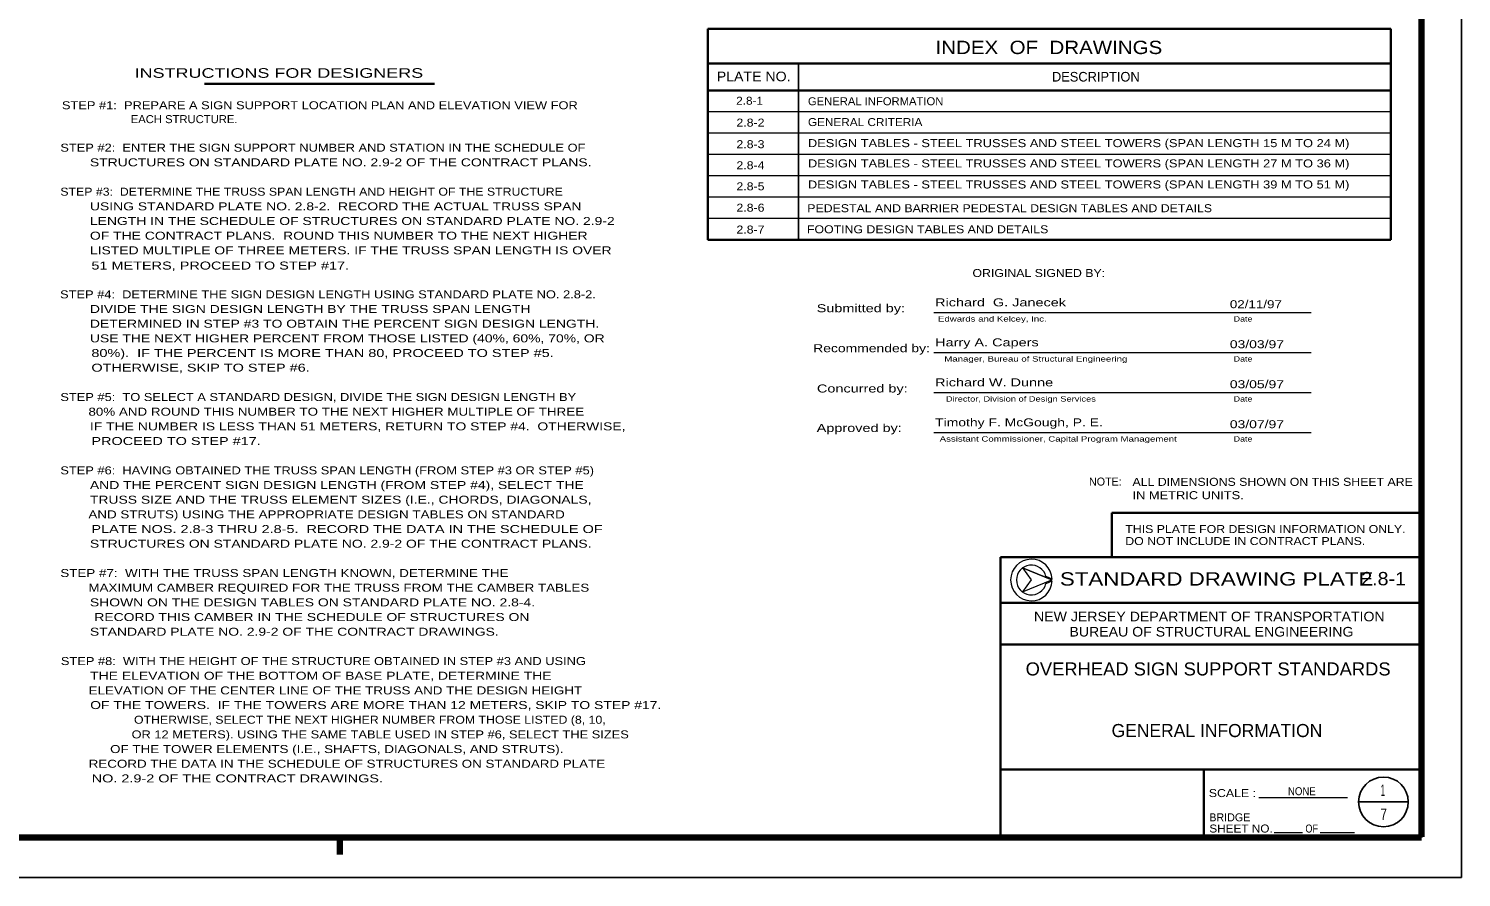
# Model space of a CAD drawing. Extents: x 312601.858 to 312602.699, y 144420.109 to 144420.704.
# Drawn here: x 312602.162 to 312602.699, y 144420.109 to 144420.428 of the extents above; entities that cross this region are included whole.
import ezdxf
from ezdxf.enums import TextEntityAlignment as Align

# ---------------------------------------------------------------- set-up
doc = ezdxf.new("R2010")
doc.units = 0
doc.header["$LTSCALE"] = 0.0012
for name, color, linetype, lineweight in [('1', 7, 'Continuous', 13), ('2', 7, 'Continuous', 25), ('39', 7, 'Continuous', 25)]:
    doc.layers.add(name, color=color, linetype=linetype, lineweight=lineweight)
doc.layers.add('4', color=7, linetype='Continuous')
doc.layers.add('51', color=7, linetype='Continuous')

msp = doc.modelspace()

# ---------------------------------------------------------------- linework, layer by layer
at = {"layer": '1', "lineweight": 35}
for p, q in [((312602.4163, 144420.3486), (312602.4163, 144420.4276)), ((312602.6724, 144420.4276), (312602.4163, 144420.4276)), ((312602.6724, 144420.3486), (312602.6724, 144420.4276)), ((312602.6724, 144420.4146), (312602.4163, 144420.4146)), ((312602.6724, 144420.4046), (312602.4163, 144420.4046)), ((312602.6724, 144420.3486), (312602.4163, 144420.3486))]:
    msp.add_line(p, q, dxfattribs=at)
at = {"layer": '1', "lineweight": 25}
msp.add_line((312602.4503, 144420.3486), (312602.4503, 144420.4146), dxfattribs=at)
at = {"layer": '1'}
for p, q in [((312602.6724, 144420.3966), (312602.4163, 144420.3966)), ((312602.6724, 144420.3886), (312602.4163, 144420.3886)), ((312602.6724, 144420.3806), (312602.4163, 144420.3806)), ((312602.6724, 144420.3726), (312602.4163, 144420.3726)), ((312602.6724, 144420.3646), (312602.4163, 144420.3646)), ((312602.6724, 144420.3566), (312602.4163, 144420.3566)), ((312602.501, 144420.3213), (312602.6425, 144420.3213)), ((312602.501, 144420.3063), (312602.6425, 144420.3063)), ((312602.501, 144420.2913), (312602.6425, 144420.2913)), ((312602.501, 144420.2763), (312602.6425, 144420.2763)), ((312602.5431, 144420.2197), (312602.5454, 144420.2207)), ((312602.6286, 144420.1263), (312602.6392, 144420.1263)), ((312602.6459, 144420.1263), (312602.6587, 144420.1263))]:
    msp.add_line(p, q, dxfattribs=at)
for points in [[(312602.5452, 144420.221), (312602.5343, 144420.2255), (312602.5452, 144420.221)], [(312602.5454, 144420.2213), (312602.5431, 144420.2223), (312602.543, 144420.2223)]]:
    msp.add_lwpolyline(points, dxfattribs=at)
for points in [[(312602.5452, 144420.221), (312602.5343, 144420.2255), (312602.5375, 144420.221), (312602.5343, 144420.2165)], [(312602.5375, 144420.221), (312602.5343, 144420.2165), (312602.5452, 144420.221), (312602.5343, 144420.2255)]]:
    msp.add_lwpolyline(points, close=True, dxfattribs=at)
for radius, start, end in [(0.0078026, 2.21392, 357.78608), (0.0056, 13.69411, 346.30589)]:
    msp.add_arc((312602.5376, 144420.221), radius, start, end, dxfattribs=at)
at = {"layer": '2', "lineweight": 35}
msp.add_line((312602.2276, 144420.407), (312602.3138, 144420.407), dxfattribs=at)
at = {"layer": '39'}
for p, q in [((312602.6988, 144420.1095), (312602.6988, 144420.7035)), ((312602.6789, 144420.1378), (312602.6603, 144420.1378)), ((312601.8578, 144420.1095), (312602.6988, 144420.1095))]:
    msp.add_line(p, q, dxfattribs=at)
at = {"layer": '39', "lineweight": 158}
for p, q in [((312602.6838, 144420.1247), (312602.6838, 144420.6645)), ((312601.9088, 144420.1245), (312602.6838, 144420.1245)), ((312602.2783, 144420.1181), (312602.2783, 144420.1245))]:
    msp.add_line(p, q, dxfattribs=at)
at = {"layer": '39', "lineweight": 35}
for p, q in [((312602.5677, 144420.2462), (312602.6838, 144420.2462)), ((312602.5677, 144420.2295), (312602.5677, 144420.2462)), ((312602.526, 144420.1245), (312602.526, 144420.2295)), ((312602.526, 144420.2124), (312602.6838, 144420.2124)), ((312602.526, 144420.1968), (312602.6838, 144420.1968)), ((312602.526, 144420.1499), (312602.6838, 144420.1499)), ((312602.6022, 144420.1248), (312602.6022, 144420.1499)), ((312602.6022, 144420.1248), (312602.6022, 144420.1499))]:
    msp.add_line(p, q, dxfattribs=at)
at = {"layer": '39', "lineweight": 13}
for p, q in [((312602.6022, 144420.1499), (312602.6838, 144420.1499)), ((312602.6229, 144420.1395), (312602.6561, 144420.1395))]:
    msp.add_line(p, q, dxfattribs=at)
at = {"layer": '39', "lineweight": 35}
msp.add_lwpolyline([(312602.526, 144420.2295), (312602.6838, 144420.2295), (312602.6838, 144420.1245)], dxfattribs=at)
at = {"layer": '39', "lineweight": 13}
msp.add_lwpolyline([(312602.5452, 144420.221), (312602.5343, 144420.2255), (312602.5375, 144420.221), (312602.5343, 144420.2165)], close=True, dxfattribs=at)
at = {"layer": '39'}
msp.add_circle((312602.6696, 144420.1378), 0.0093005, dxfattribs=at)

# ---------------------------------------------------------------- texts
at = {"layer": '2'}
for s, height, width, p in [('INDEX  OF  DRAWINGS', 0.005, 1.15, (312602.54415, 144420.4182)), ('                  INSTRUCTIONS FOR DESIGNERS', 0.0036, 1.4, (312602.2386, 144420.4093)), ('PLATE NO.', 0.0036, 1.1, (312602.43345, 144420.408)), ('PEDESTAL AND BARRIER PEDESTAL DESIGN TABLES AND DETAILS', 0.003, 1.15, (312602.52945, 144420.3589)), ('FOOTING DESIGN TABLES AND DETAILS', 0.003, 1.15, (312602.4987, 144420.351)), ('Submitted by:', 0.003, 1.35, (312602.47365, 144420.3214)), ('Edwards and Kelcey, Inc.', 0.002, 1.35, (312602.52295, 144420.3179)), ('Date', 0.002, 1.25, (312602.61695, 144420.3179)), ('Recommended by:', 0.003, 1.3, (312602.47765, 144420.3064)), ('Manager, Bureau of Structural Engineering', 0.002, 1.35, (312602.53925, 144420.3029)), ('Date', 0.002, 1.25, (312602.61695, 144420.3029)), ('Concurred by:', 0.003, 1.35, (312602.4742, 144420.2913)), ('Director, Division of Design Services', 0.002, 1.3, (312602.53365, 144420.2879)), ('Date', 0.002, 1.25, (312602.61695, 144420.2879)), ('Approved by:', 0.003, 1.35, (312602.47305, 144420.2765)), ('Assistant Commissioner, Capital Program Management', 0.002, 1.35, (312602.54765, 144420.2729)), ('Date', 0.002, 1.25, (312602.61695, 144420.2729)), ('2.8-1', 0.005, 1.1, (312602.66965, 144420.219)), ('OVERHEAD SIGN SUPPORT STANDARDS', 0.0049, 1.05, (312602.60385, 144420.1852)), ('OTHERWISE, SELECT THE NEXT HIGHER NUMBER FROM THOSE LISTED (8, 10,', 0.003, 1.15, (312602.28955, 144420.1671))]:
    msp.add_text(s, height=height, dxfattribs=dict(at, width=width)).set_placement(p, align=Align.CENTER)
for s, height, p in [('DESCRIPTION', 0.0036, (312602.56175, 144420.4079)), ('GENERAL INFORMATION', 0.0049, (312602.60715, 144420.1621))]:
    msp.add_text(s, height=height, dxfattribs=at).set_placement(p, align=Align.CENTER)
for s, width, p in [('2.8-1', 1.1, (312602.4269, 144420.3992)), ('GENERAL INFORMATION', 1.05, (312602.4538, 144420.399)), ('STEP #1:  PREPARE A SIGN SUPPORT LOCATION PLAN AND ELEVATION VIEW FOR', 1.2, (312602.1741, 144420.3975)), ('EACH STRUCTURE.', 1.05, (312602.1999, 144420.3923)), ('2.8-2', 1.15, (312602.427, 144420.391)), ('GENERAL CRITERIA', 1.1, (312602.4538, 144420.3912)), ('2.8-3', 1.15, (312602.427, 144420.3829)), ('DESIGN TABLES - STEEL TRUSSES AND STEEL TOWERS (SPAN LENGTH 15 M TO 24 M)', 1.2, (312602.4538, 144420.3833)), ('STEP #2:  ENTER THE SIGN SUPPORT NUMBER AND STATION IN THE SCHEDULE OF', 1.2, (312602.1735, 144420.3816)), ('          STRUCTURES ON STANDARD PLATE NO. 2.9-2 OF THE CONTRACT PLANS.', 1.3, (312602.1701, 144420.3761)), ('2.8-4', 1.15, (312602.427, 144420.375)), ('DESIGN TABLES - STEEL TRUSSES AND STEEL TOWERS (SPAN LENGTH 27 M TO 36 M)', 1.2, (312602.4538, 144420.3757)), ('2.8-5', 1.15, (312602.427, 144420.3671)), ('DESIGN TABLES - STEEL TRUSSES AND STEEL TOWERS (SPAN LENGTH 39 M TO 51 M)', 1.2, (312602.4538, 144420.3678)), ('STEP #3:  DETERMINE THE TRUSS SPAN LENGTH AND HEIGHT OF THE STRUCTURE', 1.15, (312602.1735, 144420.3651)), ('          USING STANDARD PLATE NO. 2.8-2.  RECORD THE ACTUAL TRUSS SPAN ', 1.3, (312602.1701, 144420.3596)), ('2.8-6', 1.15, (312602.427, 144420.3591)), ('          LENGTH IN THE SCHEDULE OF STRUCTURES ON STANDARD PLATE NO. 2.9-2 ', 1.3, (312602.1701, 144420.3541)), ('2.8-7', 1.15, (312602.427, 144420.3509)), ('          OF THE CONTRACT PLANS.  ROUND THIS NUMBER TO THE NEXT HIGHER ', 1.3, (312602.1701, 144420.3486)), ('          LISTED MULTIPLE OF THREE METERS. IF THE TRUSS SPAN LENGTH IS OVER', 1.3, (312602.1701, 144420.3431)), ('          51 METERS, PROCEED TO STEP #17.', 1.35, (312602.1701, 144420.3374)), ('STEP #4:  DETERMINE THE SIGN DESIGN LENGTH USING STANDARD PLATE NO. 2.8-2. ', 1.2, (312602.1734, 144420.3266)), ('          DIVIDE THE SIGN DESIGN LENGTH BY THE TRUSS SPAN LENGTH', 1.3, (312602.1701, 144420.3211)), ('          DETERMINED IN STEP #3 TO OBTAIN THE PERCENT SIGN DESIGN LENGTH. ', 1.3, (312602.1701, 144420.3156)), ('          USE THE NEXT HIGHER PERCENT FROM THOSE LISTED (40%, 60%, 70%, OR', 1.3, (312602.1701, 144420.3101)), ('          80%).  IF THE PERCENT IS MORE THAN 80, PROCEED TO STEP #5. ', 1.35, (312602.1701, 144420.3046)), ('          OTHERWISE, SKIP TO STEP #6.', 1.35, (312602.1701, 144420.2991)), ('STEP #5:  TO SELECT A STANDARD DESIGN, DIVIDE THE SIGN DESIGN LENGTH BY', 1.2, (312602.1735, 144420.2881)), ('          80% AND ROUND THIS NUMBER TO THE NEXT HIGHER MULTIPLE OF THREE', 1.25, (312602.1701, 144420.2826)), ('          IF THE NUMBER IS LESS THAN 51 METERS, RETURN TO STEP #4.  OTHERWISE,', 1.3, (312602.1701, 144420.2771)), ('          PROCEED TO STEP #17.', 1.35, (312602.1701, 144420.2716)), ('STEP #6:  HAVING OBTAINED THE TRUSS SPAN LENGTH (FROM STEP #3 OR STEP #5)', 1.2, (312602.1735, 144420.2606)), ('          AND THE PERCENT SIGN DESIGN LENGTH (FROM STEP #4), SELECT THE', 1.3, (312602.1701, 144420.2551)), ('          TRUSS SIZE AND THE TRUSS ELEMENT SIZES (I.E., CHORDS, DIAGONALS,', 1.3, (312602.1701, 144420.2496)), ('          AND STRUTS) USING THE APPROPRIATE DESIGN TABLES ON STANDARD', 1.25, (312602.1701, 144420.2441)), ('          PLATE NOS. 2.8-3 THRU 2.8-5.  RECORD THE DATA IN THE SCHEDULE OF', 1.35, (312602.1701, 144420.2386)), ('THIS PLATE FOR DESIGN INFORMATION ONLY.', 1.15, (312602.5728, 144420.2386)), ('          STRUCTURES ON STANDARD PLATE NO. 2.9-2 OF THE CONTRACT PLANS.', 1.3, (312602.1701, 144420.2331)), ('DO NOT INCLUDE IN CONTRACT PLANS.', 1.15, (312602.5728, 144420.2341)), ('STEP #7:  WITH THE TRUSS SPAN LENGTH KNOWN, DETERMINE THE', 1.25, (312602.1735, 144420.2221)), ('          MAXIMUM CAMBER REQUIRED FOR THE TRUSS FROM THE CAMBER TABLES', 1.25, (312602.1701, 144420.2166)), ('          SHOWN ON THE DESIGN TABLES ON STANDARD PLATE NO. 2.8-4.', 1.3, (312602.1701, 144420.2111)), ('         RECORD THIS CAMBER IN THE SCHEDULE OF STRUCTURES ON', 1.3, (312602.1732, 144420.2056)), ('          STANDARD PLATE NO. 2.9-2 OF THE CONTRACT DRAWINGS.', 1.3, (312602.1701, 144420.2001)), ('STEP #8:  WITH THE HEIGHT OF THE STRUCTURE OBTAINED IN STEP #3 AND USING', 1.2, (312602.1737, 144420.1891)), ('          THE ELEVATION OF THE BOTTOM OF BASE PLATE, DETERMINE THE', 1.3, (312602.1702, 144420.1836)), ('          ELEVATION OF THE CENTER LINE OF THE TRUSS AND THE DESIGN HEIGHT', 1.25, (312602.1702, 144420.1781)), ('          OF THE TOWERS.  IF THE TOWERS ARE MORE THAN 12 METERS, SKIP TO STEP #17.', 1.3, (312602.1702, 144420.1726)), ('OR 12 METERS). USING THE SAME TABLE USED IN STEP #6, SELECT THE SIZES', 1.2, (312602.2002, 144420.1616)), ('     OF THE TOWER ELEMENTS (I.E., SHAFTS, DIAGONALS, AND STRUTS).', 1.25, (312602.1852, 144420.1561)), ('          RECORD THE DATA IN THE SCHEDULE OF STRUCTURES ON STANDARD PLATE', 1.25, (312602.1702, 144420.1506)), ('          NO. 2.9-2 OF THE CONTRACT DRAWINGS. ', 1.35, (312602.1702, 144420.1451))]:
    msp.add_text(s, height=0.003, dxfattribs=dict(at, width=width)).set_placement(p)
at = {"layer": '39'}
for s, height, width, p in [('STANDARD DRAWING PLATE       ', 0.005, 1.25, (312602.61515, 144420.2189)), ('NEW JERSEY DEPARTMENT OF TRANSPORTATION', 0.003599, 1.1, (312602.6043, 144420.2055)), ('BUREAU OF STRUCTURAL ENGINEERING', 0.0036, 1.1, (312602.6051, 144420.1998)), ('NONE', 0.003, 0.9, (312602.639, 144420.1403)), ('SCALE :', 0.003, 1.15, (312602.61295, 144420.1396)), ('SCALE :', 0.003, 1.15, (312602.61295, 144420.1396)), ('SCALE :', 0.003, 1.15, (312602.61295, 144420.1396)), ('OF', 0.003, 0.85, (312602.6427, 144420.1263))]:
    msp.add_text(s, height=height, dxfattribs=dict(at, width=width)).set_placement(p, align=Align.CENTER)
msp.add_text('BRIDGE', height=0.003, dxfattribs=at).set_placement((312602.6043, 144420.1305))
msp.add_text('BRIDGE', height=0.003, dxfattribs=at).set_placement((312602.6043, 144420.1305))
msp.add_text('BRIDGE', height=0.003, dxfattribs=at).set_placement((312602.6043, 144420.1305))
at = {"layer": '39', "width": 1.1}
msp.add_text('SHEET NO.', height=0.003, dxfattribs=at).set_placement((312602.6043, 144420.1263))
msp.add_text('SHEET NO.', height=0.003, dxfattribs=at).set_placement((312602.6043, 144420.1263))
msp.add_text('SHEET NO.', height=0.003, dxfattribs=at).set_placement((312602.6043, 144420.1263))
at = {"layer": '4'}
for s, width, p in [('ORIGINAL SIGNED BY:', 1.15, (312602.5155, 144420.3346)), ('Richard  G. Janecek', 1.35, (312602.5015, 144420.3236)), ('02/11/97', 1.25, (312602.612, 144420.3229)), ('Harry A. Capers', 1.35, (312602.5015, 144420.3086)), ('03/03/97', 1.3, (312602.612, 144420.3079)), ('Richard W. Dunne', 1.35, (312602.5015, 144420.2936)), ('03/05/97', 1.3, (312602.612, 144420.2929)), ('Timothy F. McGough, P. E.', 1.3, (312602.5015, 144420.2786)), ('03/07/97', 1.3, (312602.612, 144420.2779)), ('ALL DIMENSIONS SHOWN ON THIS SHEET ARE', 1.15, (312602.5755, 144420.2563)), ('IN METRIC UNITS.', 1.2, (312602.5755, 144420.2513))]:
    msp.add_text(s, height=0.003, dxfattribs=dict(at, width=width)).set_placement(p)
msp.add_text('NOTE:', height=0.003, dxfattribs=at).set_placement((312602.5592, 144420.2564))
at = {"layer": '51'}
for s, width, p in [('1', 0.45, (312602.66935, 144420.14)), ('7', 0.75, (312602.6697, 144420.131))]:
    msp.add_text(s, height=0.0043, dxfattribs=dict(at, width=width)).set_placement(p, align=Align.CENTER)

doc.saveas('drawing.dxf')
